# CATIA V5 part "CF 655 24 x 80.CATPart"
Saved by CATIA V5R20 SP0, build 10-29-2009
Part number: CF 655 24 x 80
Definition: NONE
Nomenclature: CF 655 24 x 80
Source: Unknown
Description: CF 655 24 x 80
Bounding box of the stored display mesh (mm): x -57 to 23, y -22 to 22, z -22 to 22
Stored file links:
  C:\Users\Utente\Desktop\IO LAVORO\3D X SITO CF\X SITO\CF 655\CF 655 24 x 80.CATPart
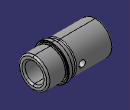
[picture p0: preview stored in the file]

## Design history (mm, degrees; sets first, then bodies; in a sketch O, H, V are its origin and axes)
Body1 "CF 655 24 x 80" (main body)
  Solid1 "CF 655 24x80": solid without history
